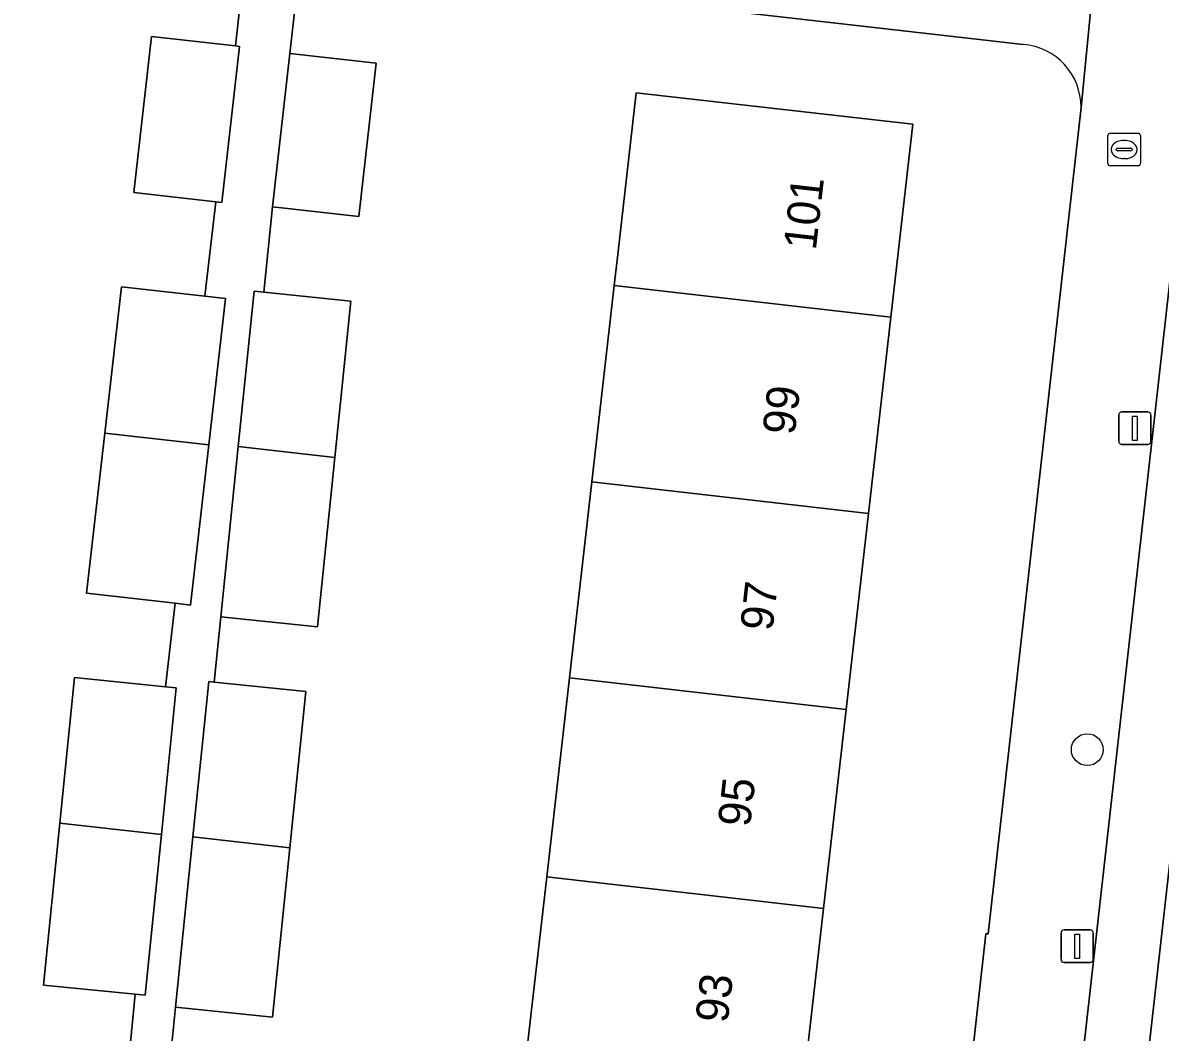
# Model space of a CAD drawing. Extents: x 161928 to 163071, y 386474 to 387428.
# Drawn here: x 162271.93 to 162306.84, y 387096.52 to 387127.5 of the extents above; entities that cross this region are included whole.
import ezdxf

# ---------------------------------------------------------------- set-up
doc = ezdxf.new("R2010")
doc.units = 0
for name, color, linetype in [('IMGEO_Boom', 7, 'Continuous'), ('IMGEO_Brandkraan', 7, 'Continuous'), ('IMGEO_Erf', 7, 'Continuous'), ('IMGEO_Lichtmast', 7, 'Continuous'), ('IMGEO_Pand', 7, 'Continuous'), ('IMGEO_Pand_nummerreeks', 7, 'Continuous'), ('IMGEO_Parkeervlak_open', 7, 'Continuous'), ('IMGEO_Rijbaan_lokaal_open', 7, 'Continuous'), ('IMGEO_Voetpad_open', 7, 'Continuous')]:
    doc.layers.add(name, color=color, linetype=linetype)

msp = doc.modelspace()

# ---------------------------------------------------------------- linework, layer by layer
at = {"layer": 'IMGEO_Boom'}
msp.add_circle((162304.599, 387105.195), 0.489, dxfattribs=at)
at = {"layer": 'IMGEO_Brandkraan'}
for p, q in [((162305.23, 387123.185), (162305.23, 387124.037)), ((162305.305, 387124.111), (162306.157, 387124.111)), ((162305.718, 387123.891), (162305.743, 387123.891)), ((162306.231, 387124.037), (162306.231, 387123.185)), ((162305.489, 387123.605), (162305.489, 387123.617)), ((162305.927, 387123.568), (162305.529, 387123.568)), ((162305.532, 387123.654), (162305.93, 387123.654)), ((162305.973, 387123.617), (162305.973, 387123.605)), ((162306.157, 387123.111), (162305.305, 387123.111)), ((162305.741, 387123.331), (162305.716, 387123.331))]:
    msp.add_line(p, q, dxfattribs=at)
for points in [[(162305.23, 387123.185), (162305.23, 387124.037)], [(162305.305, 387124.111), (162306.157, 387124.111)], [(162306.231, 387124.037), (162306.231, 387123.185)], [(162306.157, 387123.111), (162305.305, 387123.111)]]:
    msp.add_lwpolyline(points, dxfattribs=at)
for centre, radius, start, end in [((162305.307, 387124.035), 0.0765, 91.552, 178.448), ((162305.307, 387124.035), 0.0765, 91.552, 178.448), ((162306.155, 387124.035), 0.0765, 1.552, 88.448), ((162306.155, 387124.035), 0.0765, 1.552, 88.448), ((162305.529, 387123.614), 0.0403, 85.8775, 175.7526), ((162305.526, 387123.604), 0.0366, 178.938, 274.7102), ((162305.93, 387123.611), 0.043, 264.8664, 352.4533), ((162305.934, 387123.616), 0.0386, 1.7309, 96.639), ((162305.307, 387123.187), 0.0765, 181.552, 268.448), ((162305.307, 387123.187), 0.0765, 181.552, 268.448), ((162306.155, 387123.187), 0.0765, 271.552, 358.448), ((162306.155, 387123.187), 0.0765, 271.552, 358.448)]:
    msp.add_arc(centre, radius, start, end, dxfattribs=at)
for centre, major_axis, ratio, start_param, end_param in [((162305.717, 387123.611), (-0.387, 0.002), 0.722429, 4.712389, 7.853982), ((162305.742, 387123.611), (-0.39, 0.002), 0.717154, 1.570796, 4.712389)]:
    msp.add_ellipse(centre, major_axis=major_axis, ratio=ratio, start_param=start_param, end_param=end_param, dxfattribs=at)
at = {"layer": 'IMGEO_Erf'}
for points in [[(162273.074, 387102.935), (162273.524, 387107.409), (162276.318, 387107.128), (162276.612, 387109.687), (162273.892, 387109.999), (162274.454, 387114.905), (162274.969, 387119.401), (162277.525, 387119.109), (162277.857, 387122.01), (162275.347, 387122.291), (162275.883, 387127.078), (162278.459, 387126.789), (162278.771, 387129.566), (162258.728, 387131.864)], [(162256.634, 387130.312), (162250.249, 387072.075), (162266.748, 387070.428), (162267.197, 387074.654), (162269.978, 387077.034), (162270.199, 387079.111), (162270.688, 387083.709), (162273.758, 387083.382), (162274.026, 387085.889), (162271.837, 387086.14), (162272.377, 387090.838), (162272.925, 387095.619), (162275.154, 387095.364), (162275.388, 387097.691), (162272.575, 387097.974), (162273.074, 387102.935)], [(162302.632, 387126.832), (162300.751, 387127.046), (162280.448, 387129.374), (162280.126, 387126.561), (162282.774, 387126.265), (162282.247, 387121.553), (162279.599, 387121.85), (162279.33, 387119.229), (162282.004, 387118.955), (162281.512, 387114.157), (162280.981, 387108.966), (162278.008, 387109.271), (162277.803, 387107.269), (162280.618, 387106.98), (162280.126, 387102.182), (162279.595, 387096.991), (162276.622, 387097.296), (162276.413, 387095.248)], [(162301.491, 387099.547), (162301.553, 387099.54), (162304.407, 387124.9)], [(162297.867, 387067.105), (162301.491, 387099.547)]]:
    msp.add_lwpolyline(points, dxfattribs=at)
msp.add_lwpolyline([(162288.012, 387101.294), (162288.709, 387107.398), (162289.395, 387113.41), (162290.082, 387119.436), (162290.191, 387120.387), (162290.758, 387125.354), (162299.25, 387124.385), (162298.574, 387118.466), (162297.887, 387112.441), (162297.201, 387106.428), (162296.504, 387100.324), (162295.805, 387094.201), (162295.142, 387088.393), (162294.449, 387082.317), (162293.779, 387076.446), (162293.072, 387070.251), (162288.105, 387070.818), (162284.58, 387071.22), (162285.287, 387077.415), (162285.957, 387083.286), (162286.65, 387089.363), (162287.313, 387095.17)], close=True, dxfattribs=at)
msp.add_arc((162302.49, 387124.92), 1.917, 359.3927, 85.757, dxfattribs=at)
at = {"layer": 'IMGEO_Lichtmast'}
for p, q in [((162305.564, 387114.657), (162305.564, 387115.457)), ((162305.564, 387115.457), (162305.564, 387114.657)), ((162305.664, 387115.557), (162306.454, 387115.557)), ((162306.454, 387115.557), (162305.664, 387115.557)), ((162306.554, 387115.457), (162306.554, 387114.657)), ((162306.554, 387114.657), (162306.554, 387115.457)), ((162306.454, 387114.557), (162305.664, 387114.557)), ((162305.664, 387114.557), (162306.454, 387114.557)), ((162303.793, 387098.762), (162303.793, 387099.562)), ((162303.793, 387099.562), (162303.793, 387098.762)), ((162303.893, 387099.662), (162304.683, 387099.662)), ((162304.683, 387099.662), (162303.893, 387099.662)), ((162304.783, 387099.562), (162304.783, 387098.762)), ((162304.783, 387098.762), (162304.783, 387099.562)), ((162304.683, 387098.662), (162303.893, 387098.662)), ((162303.893, 387098.662), (162304.683, 387098.662))]:
    msp.add_line(p, q, dxfattribs=at)
for points in [[(162305.984, 387115.432), (162306.134, 387115.432), (162306.134, 387114.682), (162305.984, 387114.682), (162305.984, 387115.432)], [(162304.213, 387099.537), (162304.363, 387099.537), (162304.363, 387098.787), (162304.213, 387098.787), (162304.213, 387099.537)]]:
    msp.add_lwpolyline(points, dxfattribs=at)
for centre, start, end in [((162305.664, 387115.457), 90, 180), ((162305.664, 387115.457), 90, 180), ((162306.454, 387115.457), 0, 90), ((162306.454, 387115.457), 360, 90), ((162305.664, 387114.657), 180, 270), ((162305.664, 387114.657), 180, 270), ((162306.454, 387114.657), 270, 0), ((162306.454, 387114.657), 270, 0), ((162303.893, 387099.562), 90, 180), ((162303.893, 387099.562), 90, 180), ((162304.683, 387099.562), 0, 90), ((162304.683, 387099.562), 360, 90), ((162303.893, 387098.762), 180, 270), ((162303.893, 387098.762), 180, 270), ((162304.683, 387098.762), 270, 0), ((162304.683, 387098.762), 270, 0)]:
    msp.add_arc(centre, 0.1, start, end, dxfattribs=at)
at = {"layer": 'IMGEO_Pand'}
for points in [[(162278.583, 387126.775), (162278.459, 387126.789), (162275.883, 387127.078), (162275.347, 387122.291), (162277.857, 387122.01), (162278.047, 387121.989)], [(162282.774, 387126.265), (162280.126, 387126.561), (162279.599, 387121.85), (162282.247, 387121.553)], [(162298.574, 387118.466), (162299.25, 387124.385), (162290.758, 387125.354), (162290.191, 387120.387), (162290.082, 387119.436)], [(162278.159, 387119.036), (162277.525, 387119.109), (162274.969, 387119.401), (162274.454, 387114.905), (162277.645, 387114.552)], [(162290.082, 387119.436), (162289.395, 387113.41), (162297.887, 387112.441), (162298.574, 387118.466)], [(162282.004, 387118.955), (162279.33, 387119.229), (162279.031, 387119.26), (162278.543, 387114.496), (162281.512, 387114.157)], [(162277.645, 387114.552), (162274.454, 387114.905), (162273.892, 387109.999), (162276.612, 387109.687), (162277.082, 387109.633)], [(162278.008, 387109.271), (162280.981, 387108.966), (162281.512, 387114.157), (162278.543, 387114.496)], [(162297.201, 387106.428), (162297.887, 387112.441), (162289.395, 387113.41), (162288.709, 387107.398)], [(162276.643, 387107.095), (162276.318, 387107.128), (162273.524, 387107.409), (162273.074, 387102.935), (162276.19, 387102.591)], [(162280.618, 387106.98), (162277.803, 387107.269), (162277.645, 387107.285), (162277.157, 387102.521), (162280.126, 387102.182)], [(162288.709, 387107.398), (162288.012, 387101.294), (162296.504, 387100.324), (162297.201, 387106.428)], [(162276.19, 387102.591), (162273.074, 387102.935), (162272.575, 387097.974), (162275.388, 387097.691), (162275.694, 387097.66)], [(162276.622, 387097.296), (162279.595, 387096.991), (162280.126, 387102.182), (162277.157, 387102.521)], [(162288.012, 387101.294), (162287.313, 387095.17), (162295.805, 387094.201), (162296.504, 387100.324)]]:
    msp.add_lwpolyline(points, close=True, dxfattribs=at)
at = {"layer": 'IMGEO_Parkeervlak_open'}
for points in [[(162300.517, 387042.959), (162309.861, 387125.998)], [(162307.745, 387125.029), (162298.684, 387044.352)]]:
    msp.add_lwpolyline(points, dxfattribs=at)
at = {"layer": 'IMGEO_Rijbaan_lokaal_open'}
msp.add_lwpolyline([(162314.145, 387128.5), (162315.714, 387142.532), (162315.978, 387144.787), (162316.222, 387146.882), (162320.968, 387189.478), (162322.961, 387207.382), (162328.575, 387257.733), (162324.595, 387258.179), (162324.485, 387257.3), (162314.527, 387167.729), (162311.851, 387143.8), (162310.201, 387129.087), (162309.861, 387125.998), (162300.517, 387042.959), (162300.407, 387041.864)], dxfattribs=at)
at = {"layer": 'IMGEO_Voetpad_open'}
for points in [[(162252.493, 387140.143), (162252.553, 387140.72), (162247.291, 387141.304), (162247.235, 387140.763), (162242.055, 387141.336), (162241.791, 387138.914), (162246.765, 387138.42), (162246.201, 387133.316), (162248.153, 387133.076), (162251.707, 387132.639), (162252.51, 387132.54), (162258.728, 387131.864), (162278.771, 387129.566), (162280.448, 387129.374), (162300.751, 387127.046), (162302.632, 387126.832)], [(162304.929, 387130.235), (162304.407, 387124.9), (162301.553, 387099.54), (162301.491, 387099.547), (162297.867, 387067.105), (162297.677, 387065.408), (162295.188, 387043.126), (162294.536, 387036.209)], [(162304.407, 387124.9), (162304.929, 387130.235)], [(162278.771, 387129.566), (162278.459, 387126.789), (162278.583, 387126.775), (162278.047, 387121.989), (162277.857, 387122.01), (162277.525, 387119.109), (162278.159, 387119.036), (162277.645, 387114.552), (162277.082, 387109.633), (162276.612, 387109.687), (162276.318, 387107.128), (162276.643, 387107.095), (162276.19, 387102.591), (162275.694, 387097.66), (162275.388, 387097.691), (162275.154, 387095.364)], [(162276.413, 387095.248), (162276.622, 387097.296), (162277.157, 387102.521), (162277.645, 387107.285), (162277.803, 387107.269), (162278.008, 387109.271), (162278.543, 387114.496), (162279.031, 387119.26), (162279.33, 387119.229), (162279.599, 387121.85), (162280.126, 387126.561), (162280.448, 387129.374)], [(162298.684, 387044.352), (162307.745, 387125.029)]]:
    msp.add_lwpolyline(points, dxfattribs=at)
msp.add_arc((162302.49, 387124.92), 1.917, 359.3927, 85.757, dxfattribs=at)

# ---------------------------------------------------------------- texts
at = {"layer": 'IMGEO_Pand_nummerreeks'}
for s, p in [('101', (162296.269, 387120.498)), ('99', (162295.623, 387114.827)), ('97', (162294.937, 387108.813)), ('95', (162294.25, 387102.798)), ('93', (162293.564, 387096.783))]:
    msp.add_text(s, height=1, rotation=83.4893, dxfattribs=at).set_placement(p)

doc.saveas('drawing.dxf')
